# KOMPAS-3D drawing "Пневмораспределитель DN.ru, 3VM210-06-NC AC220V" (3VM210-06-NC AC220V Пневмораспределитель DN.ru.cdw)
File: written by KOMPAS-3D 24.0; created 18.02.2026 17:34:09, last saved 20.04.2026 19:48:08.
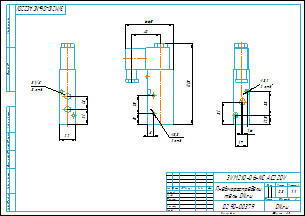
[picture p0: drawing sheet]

Document properties: Автор: R2D2; Форматы листов документа: A3; Полное имя файла: 3VM210-06-NC AC220V Пневмораспределитель DN.ru.m3d; Масса: 0.3; Наименование: Пневмораспределитель DN.ru; Количество листов документа: 1; Примечание: D290-00379

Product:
- Part/product: Пневмораспределитель DN.ru  | designation 3VM210-06-NC AC220V
    Масса: 0.3
    Раздел спецификации: Прочие изделия
    Форматы листов документа: A3
    Примечание: D290-00379

Views: Вид 1, Спереди, Проекционный вид 2, Проекционный вид 3
Referenced files in E:\Работа\Зайцев\Аксессуары для пневмоприводов\Пневмораспределители DN.ru\3VM210-06-NC Пневмораспределитель DN.RU\AC24V\: 3VM210-06-NC AC24V Пневмораспределитель DN.ru.m3d
Referenced files in E:\Работа\Зайцев\Аксессуары для пневмоприводов\Пневмораспределители DN.ru\3VM210-06-NC Пневмораспределитель DN.RU\AC220V\: 3VM210-06-NC AC220V Пневмораспределитель DN.ru.m3d
Referenced files in E:\Работа\Зайцев\Для компаса\: чертеж DN.ru А3.cdt
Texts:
  Линейный размер
  чертеж DN.ru А3.cdt
  Пневмораспредели
  тель DN.ru
  Пневмораспределитель DN.ru
  3VM210-06-NC AC220V Пневмораспределитель DN.ru
Dimensions and other numbers on the sheet: 0; 3; 2; 4; 3 отв.; 21; 18; 22; 3VM210-06-NC AC220V; 66,5; 40; 111,5; 3,3; 2 отв.; 15; 25; 8; 3,2; 33; 12,5; 17; 1,6; 31; 1:1; 1; 0,3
